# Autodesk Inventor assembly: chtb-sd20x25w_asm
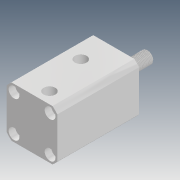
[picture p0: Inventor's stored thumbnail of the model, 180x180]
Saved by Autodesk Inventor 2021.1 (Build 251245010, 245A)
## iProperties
Company: Microsoft
Created: 2018-05
Part Number: chtb-sd20x25w_asm
Description: STEP AP214
Document SubType Name: Assembly
Designer: user
Title: chtb-sd20x25w_asm.STEP
Author: Windows
Revision Number: ÈÎºÎ
Sending System: SolidWorks 2015
Preprocessor: SwSTEP 2.0
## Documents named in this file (4)
- D:\Vault_2016\Projekty\Clamptek\Hydraulic\CHTB\CHTB-20\Inventor\CHTB-SD20x25W\chtb-sd20x25w_asm.iam
- D:\Vault_2016\Projekty\Clamptek\Hydraulic\CHTB\CHTB-20\Inventor\CHTB-SD20x25W\CHTB-SD20X25NBT.ipt
- D:\Vault_2016\Projekty\Clamptek\Hydraulic\CHTB\CHTB-20\Inventor\CHTB-SD20x25W\CHTB-SD20X25WHSG.ipt
- D:\Vault_2016\Projekty\Clamptek\Hydraulic\CHTB\CHTB-20\Inventor\CHTB-SD20x25W\QG.ipt
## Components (3 placed, 3 different names)
1. CHTB-SD20X25NBT_1
2. CHTB-SD20X25WHSG_2
3. QG_3
